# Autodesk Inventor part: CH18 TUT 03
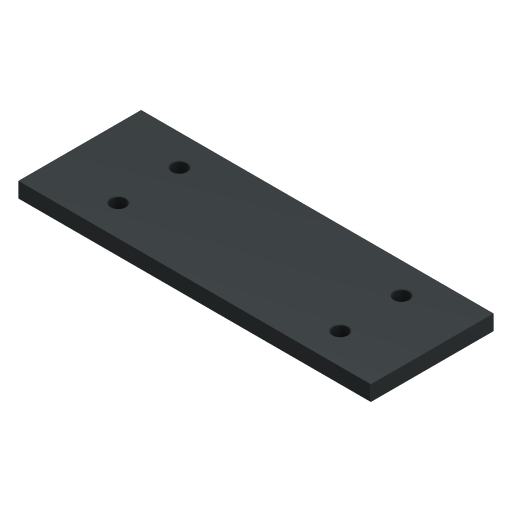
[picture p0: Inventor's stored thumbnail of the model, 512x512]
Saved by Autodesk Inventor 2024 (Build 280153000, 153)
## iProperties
Created: 2016-05
Part Number: CH18 TUT 03
Material: Iron, Cast
Document SubType Name: Modeling
Designer: CADCIM
Density: 7.15 g/cm^3
Appearance: Iron Gray
Mass: 161.642 g
Surface Area: 109.071 cm^2
Volume: 22.6073 cm^3
Author: CADCIM
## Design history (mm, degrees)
sketch "Sketch1"
  geometry: L1 (0, 40)-(115, 40); L2 (115, 40)-(115, 0); L3 (115, 0)-(0, 0); L4 (0, 0)-(0, 40); C1 r 2.5 at (22.5, 30); C2 r 2.5 at (95, 30); C3 r 2.5 at (22.5, 10); C4 r 2.5 at (95, 10); 1 further point
  constraints: 8 end point, 4 centre point, 2 horizontal, 2 parallel, 1 coincident, 1 perpendicular, 1 vertical, 6 other
  dimensions: "d0" = 115 distance of L1.start L1.end; "d1" = 40 distance of L1.end L2.end; "d2" = 10 distance from line of L1 C1.centre; "d3" = 22.5 distance from line of L4 C1.centre; "d6" = 72.5 distance of C1.centre C2.centre; "d9" = 20 distance of C1.centre C3.centre; "d14" = 5 diameter of C2
extrude "Extrusion1" new body sketch "Sketch1" distance "d12" = 5; taper "d13" = 0 deg
body "Solid1"
